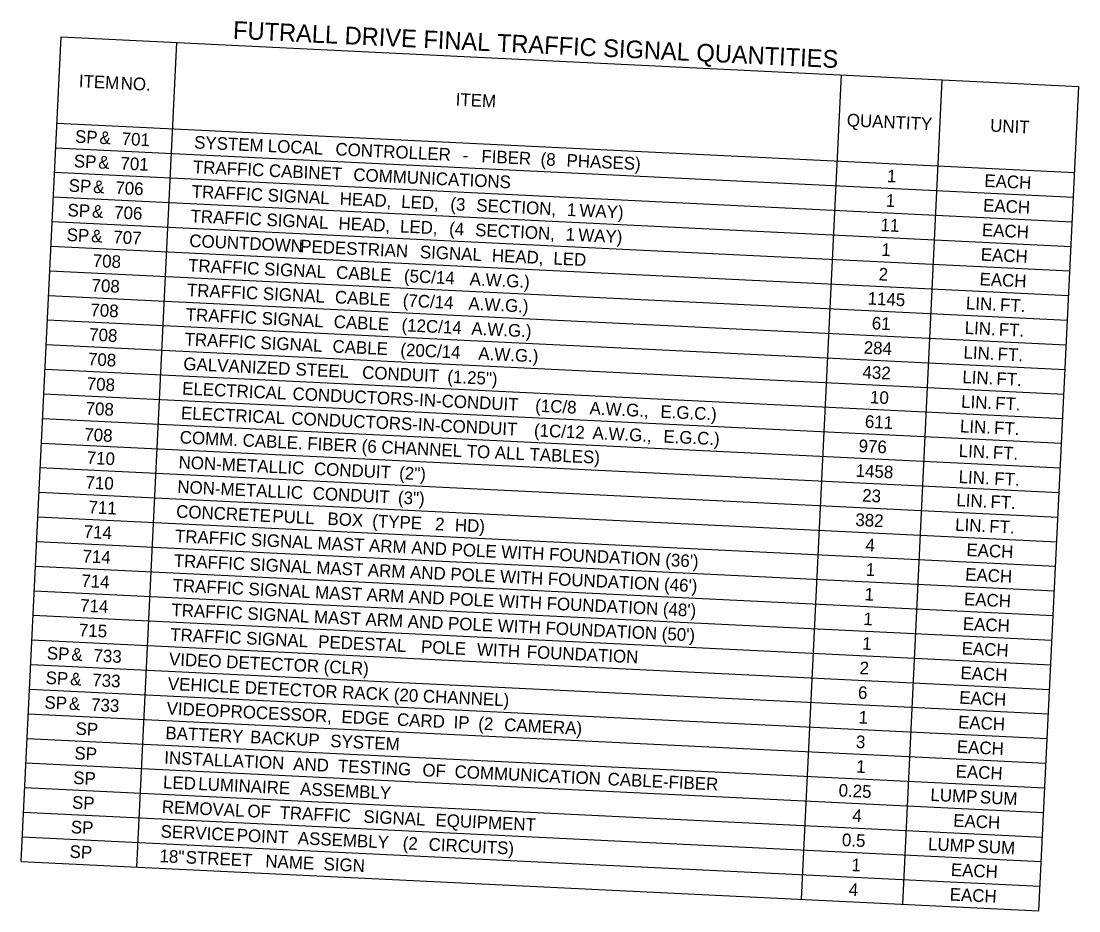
# Model space of a CAD drawing. Extents: x 661018 to 663325, y 642537 to 643074.
# Drawn here: x 661027.9 to 661230.7, y 642822.1 to 642992.7 of the extents above; entities that cross this region are included whole.
import ezdxf

# ---------------------------------------------------------------- set-up
doc = ezdxf.new("R2010")
doc.units = 0
doc.layers.add('R_Border Notes', color=7, linetype='Continuous')

msp = doc.modelspace()

# ---------------------------------------------------------------- linework, layer by layer
at = {"layer": 'R_Border Notes'}
for p, q in [((661027.92, 642831.61), (661035.6, 642989.63)), ((661035.6, 642989.63), (661230.69, 642980.15)), ((661050.12, 642830.53), (661057.77, 642988.55)), ((661177.55, 642824.34), (661185.17, 642982.36)), ((661196.93, 642823.4), (661204.51, 642981.42)), ((661223.01, 642822.13), (661230.69, 642980.15)), ((661034.8, 642973.12), (661229.89, 642963.64)), ((661034.57, 642968.4), (661229.66, 642958.93)), ((661034.34, 642963.68), (661229.43, 642954.21)), ((661034.11, 642958.96), (661229.2, 642949.49)), ((661033.88, 642954.25), (661228.97, 642944.77)), ((661033.65, 642949.53), (661228.74, 642940.06)), ((661033.42, 642944.81), (661228.51, 642935.34)), ((661033.19, 642940.1), (661228.28, 642930.62)), ((661032.96, 642935.38), (661228.05, 642925.91)), ((661032.73, 642930.66), (661227.82, 642921.19)), ((661032.51, 642925.95), (661227.6, 642916.47)), ((661032.51, 642925.95), (661227.6, 642916.47)), ((661032.28, 642921.23), (661227.37, 642911.75)), ((661032.05, 642916.51), (661227.14, 642907.04)), ((661031.82, 642911.79), (661226.91, 642902.32)), ((661031.59, 642907.08), (661226.68, 642897.6)), ((661031.36, 642902.36), (661226.45, 642892.89)), ((661031.13, 642897.64), (661226.22, 642888.17)), ((661030.9, 642892.93), (661225.99, 642883.45)), ((661030.67, 642888.21), (661225.76, 642878.74)), ((661030.44, 642883.49), (661225.53, 642874.02)), ((661030.21, 642878.78), (661225.31, 642869.3)), ((661029.99, 642874.06), (661225.08, 642864.58)), ((661029.76, 642869.34), (661224.85, 642859.87)), ((661029.53, 642864.62), (661224.62, 642855.15)), ((661029.3, 642859.91), (661224.39, 642850.43)), ((661029.07, 642855.19), (661224.16, 642845.72)), ((661029.07, 642855.19), (661224.16, 642845.72)), ((661028.84, 642850.47), (661223.93, 642841)), ((661028.61, 642845.76), (661223.7, 642836.28)), ((661028.38, 642841.04), (661223.47, 642831.57)), ((661028.15, 642836.32), (661223.24, 642826.85)), ((661027.92, 642831.61), (661223.01, 642822.13)), ((661027.92, 642831.61), (661223.01, 642822.13))]:
    msp.add_line(p, q, dxfattribs=at)

# ---------------------------------------------------------------- texts
for s, height, p in [('FUTRALL DRIVE FINAL TRAFFIC SIGNAL QUANTITIES', 3.3906, (661068.48, 642989.29)), ('ITEM', 2.422, (661038.94, 642979.98)), (' NO.', 2.422, (661046.06, 642979.63)), ('ITEM', 2.422, (661111.18, 642976.47)), ('QUANTITY', 2.422, (661186.16, 642972.52)), ('UNIT', 2.422, (661213.64, 642971.49)), ('SP', 2.422, (661038.21, 642969.37)), (' &', 2.422, (661042, 642969.19)), (' 701', 2.422, (661046.25, 642968.98)), ('SYSTEM', 2.422, (661061.04, 642968.26)), (' LOCAL', 2.422, (661074.26, 642967.62)), (' CONTROLLER', 2.4218, (661087.23, 642966.99)), ('SP', 2.422, (661037.98, 642964.66)), (' FIBER', 2.422, (661115.21, 642965.63)), (' (8', 2.422, (661126.56, 642965.08)), (' PHASES)', 2.422, (661131.53, 642964.84)), (' &', 2.422, (661041.77, 642964.47)), (' 701', 2.422, (661046.02, 642964.27)), ('TRAFFIC', 2.422, (661060.81, 642963.55)), (' CABINET', 2.422, (661074.47, 642962.88)), (' -', 2.422, (661111.61, 642965.81)), (' COMMUNICATIONS', 2.4218, (661090.66, 642962.1)), ('1', 2.42, (661193.86, 642961.81)), ('EACH', 2.422, (661212.53, 642960.91)), ('SP', 2.422, (661037, 642959.98)), (' &', 2.422, (661040.79, 642959.79)), (' 706', 2.422, (661045.04, 642959.59)), ('TRAFFIC', 2.422, (661060.58, 642958.83)), (' SIGNAL', 2.422, (661074.24, 642958.17)), (' HEAD,', 2.422, (661088.05, 642957.5)), (' LED,', 2.422, (661099.84, 642956.92)), (' (3', 2.422, (661109.26, 642956.47)), ('1', 2.42, (661193.63, 642957.1)), ('SP', 2.422, (661036.77, 642955.26)), (' &', 2.422, (661040.56, 642955.07)), (' 706', 2.422, (661044.81, 642954.87)), (' SECTION,', 2.422, (661114.24, 642956.23)), (' 1', 2.422, (661131.59, 642955.38)), (' WAY)', 2.422, (661134.01, 642955.27)), ('EACH', 2.422, (661212.3, 642956.19)), ('TRAFFIC', 2.422, (661060.35, 642954.11)), (' SIGNAL', 2.422, (661074.01, 642953.45)), (' HEAD,', 2.422, (661087.82, 642952.78)), ('11', 2.422, (661192.61, 642952.42)), ('SP', 2.422, (661036.61, 642950.54)), (' LED,', 2.422, (661099.61, 642952.21)), (' (4', 2.422, (661109.03, 642951.75)), (' SECTION,', 2.422, (661114.01, 642951.51)), (' 1', 2.422, (661131.36, 642950.67)), (' WAY)', 2.422, (661133.78, 642950.55)), ('EACH', 2.422, (661212.07, 642951.47)), (' &', 2.422, (661040.4, 642950.35)), (' 707', 2.422, (661044.65, 642950.15)), ('COUNTDOWN', 2.422, (661060.12, 642949.4)), (' PEDESTRIAN', 2.4218, (661080.48, 642948.41)), (' SIGNAL', 2.422, (661103.42, 642947.29)), (' HEAD,', 2.422, (661117.22, 642946.62)), ('1', 2.42, (661192.78, 642947.68)), ('EACH', 2.422, (661211.84, 642946.76)), ('708', 2.422, (661041.61, 642945.57)), ('TRAFFIC', 2.422, (661059.89, 642944.68)), (' LED', 2.422, (661129.01, 642946.05)), (' SIGNAL', 2.422, (661073.55, 642944.02)), (' CABLE', 2.422, (661087.36, 642943.35)), (' (5C/14', 2.422, (661100.37, 642942.71)), ('2', 2.42, (661192.26, 642942.98)), ('708', 2.422, (661041.38, 642940.85)), (' A.W.G.)', 2.422, (661112.96, 642942.1)), ('EACH', 2.422, (661211.61, 642942.04)), ('TRAFFIC', 2.422, (661059.66, 642939.96)), (' SIGNAL', 2.422, (661073.32, 642939.3)), (' CABLE', 2.422, (661087.13, 642938.63)), ('1145', 2.422, (661190.15, 642938.35)), (' (7C/14', 2.422, (661100.14, 642938)), (' A.W.G.)', 2.422, (661112.73, 642937.39)), ('LIN.', 2.422, (661208.99, 642937.44)), (' FT.', 2.422, (661214.63, 642937.17)), ('708', 2.422, (661041.15, 642936.13)), ('TRAFFIC', 2.422, (661059.43, 642935.25)), (' SIGNAL', 2.422, (661073.09, 642934.58)), (' CABLE', 2.422, (661086.9, 642933.91)), (' (12C/14', 2.422, (661099.91, 642933.28)), (' A.W.G.)', 2.422, (661113.3, 642932.63)), ('61', 2.422, (661190.95, 642933.59)), ('LIN.', 2.422, (661208.76, 642932.72)), (' FT.', 2.422, (661214.4, 642932.45)), ('708', 2.422, (661040.92, 642931.42)), ('TRAFFIC', 2.422, (661059.21, 642930.53)), (' SIGNAL', 2.422, (661072.86, 642929.87)), (' CABLE', 2.422, (661086.67, 642929.2)), (' (20C/14', 2.422, (661099.68, 642928.56)), ('284', 2.422, (661189.4, 642928.93)), ('708', 2.422, (661040.69, 642926.7)), (' A.W.G.)', 2.422, (661114.63, 642927.84)), ('LIN.', 2.422, (661208.53, 642928.01)), (' FT.', 2.422, (661214.17, 642927.73)), ('GALVANIZED', 2.422, (661058.98, 642925.81)), (' STEEL', 2.422, (661079.57, 642924.81)), (' CONDUIT', 2.422, (661092.35, 642924.19)), ('432', 2.422, (661189.17, 642924.22)), ('708', 2.422, (661040.46, 642921.98)), (' (1.25")', 2.422, (661108.69, 642923.4)), ('LIN.', 2.422, (661208.31, 642923.29)), (' FT.', 2.422, (661213.94, 642923.01)), ('ELECTRICAL', 2.422, (661058.75, 642921.09)), (' CONDUCTORS-IN-CONDUIT', 2.4218, (661079.01, 642920.11)), (' (1C/8', 2.422, (661125.53, 642917.85)), ('10', 2.422, (661190.61, 642919.42)), ('LIN.', 2.422, (661208.08, 642918.57)), (' FT.', 2.422, (661213.71, 642918.3)), ('708', 2.422, (661040.24, 642917.27)), ('ELECTRICAL', 2.422, (661058.52, 642916.38)), (' A.W.G.,', 2.422, (661135.95, 642917.35)), (' E.G.C.)', 2.422, (661149.53, 642916.69)), (' CONDUCTORS-IN-CONDUIT', 2.4218, (661078.78, 642915.39)), ('611', 2.422, (661189.63, 642914.74)), ('LIN.', 2.422, (661207.85, 642913.85)), ('708', 2.422, (661039.99, 642912.26)), (' (1C/12', 2.422, (661125.3, 642913.13)), (' A.W.G.,', 2.422, (661136.52, 642912.59)), (' E.G.C.)', 2.422, (661150.1, 642911.93)), (' FT.', 2.422, (661213.49, 642913.58)), ('COMM. CABLE. FIBER (6 CHANNEL TO ALL TABLES)', 2.4218, (661058.29, 642911.73)), ('976', 2.422, (661188.42, 642910.07)), ('710', 2.422, (661040.45, 642907.8)), ('LIN.', 2.422, (661207.62, 642909.14)), (' FT.', 2.422, (661213.26, 642908.86)), ('NON-METALLIC', 2.4218, (661058.06, 642906.94)), (' CONDUIT', 2.422, (661083.11, 642905.73)), (' (2")', 2.422, (661099.45, 642904.93)), ('1458', 2.422, (661187.86, 642905.34)), ('LIN. FT.', 2.422, (661207.6, 642904.14)), ('710', 2.422, (661040.22, 642903.08)), ('NON-METALLIC', 2.4218, (661057.83, 642902.23)), (' CONDUIT', 2.422, (661082.88, 642901.01)), (' (3")', 2.422, (661099.22, 642900.22)), ('23', 2.422, (661189.11, 642900.58)), ('LIN.', 2.422, (661207.16, 642899.7)), ('711', 2.422, (661040.79, 642898.33)), (' FT.', 2.422, (661212.8, 642899.43)), ('CONCRETE', 2.422, (661057.6, 642897.51)), (' PULL', 2.422, (661075.13, 642896.66)), (' BOX', 2.422, (661085.7, 642896.15)), (' (TYPE', 2.422, (661094.29, 642895.73)), ('382', 2.422, (661187.8, 642895.92)), ('714', 2.422, (661039.87, 642893.64)), (' 2', 2.422, (661106.34, 642895.14)), (' HD)', 2.422, (661110.13, 642894.96)), ('LIN.', 2.422, (661206.93, 642894.99)), (' FT.', 2.422, (661212.57, 642894.71)), ("TRAFFIC SIGNAL MAST ARM AND POLE WITH FOUNDATION (36')", 2.4218, (661057.37, 642892.79)), ('4', 2.42, (661189.74, 642891.09)), ('EACH', 2.422, (661209.09, 642890.15)), ('714', 2.422, (661039.64, 642888.93)), ("TRAFFIC SIGNAL MAST ARM AND POLE WITH FOUNDATION (46')", 2.4218, (661057.14, 642888.08)), ('1', 2.42, (661189.8, 642886.36)), ('714', 2.422, (661039.41, 642884.21)), ('EACH', 2.422, (661208.86, 642885.44)), ("TRAFFIC SIGNAL MAST ARM AND POLE WITH FOUNDATION (48')", 2.4218, (661056.91, 642883.36)), ('1', 2.42, (661189.57, 642881.65)), ('714', 2.422, (661039.18, 642879.49)), ('EACH', 2.422, (661208.63, 642880.72)), ("TRAFFIC SIGNAL MAST ARM AND POLE WITH FOUNDATION (50')", 2.4218, (661056.69, 642878.64)), ('1', 2.42, (661189.34, 642876.93)), ('EACH', 2.422, (661208.41, 642876)), ('715', 2.422, (661038.95, 642874.77)), ('TRAFFIC', 2.422, (661056.46, 642873.92)), (' SIGNAL', 2.422, (661070.11, 642873.26)), (' PEDESTAL', 2.422, (661083.92, 642872.59)), (' POLE', 2.422, (661103.64, 642871.63)), ('1', 2.42, (661189.11, 642872.21)), ('EACH', 2.422, (661208.18, 642871.29)), ('SP', 2.422, (661032.81, 642870.34)), (' &', 2.422, (661036.6, 642870.16)), (' 733', 2.422, (661040.85, 642869.95)), (' WITH', 2.422, (661114.36, 642871.11)), (' FOUNDATION', 2.4218, (661123.9, 642870.65)), ('VIDEO DETECTOR (CLR)', 2.4218, (661056.23, 642869.21)), ('2', 2.42, (661188.6, 642867.51)), ('SP', 2.422, (661032.58, 642865.63)), (' &', 2.422, (661036.37, 642865.44)), (' 733', 2.422, (661040.62, 642865.24)), ('EACH', 2.422, (661207.95, 642866.57)), ('VEHICLE DETECTOR RACK (20 CHANNEL)', 2.4218, (661056, 642864.49)), ('6', 2.42, (661188.3, 642862.79)), ('EACH', 2.422, (661207.72, 642861.85)), ('SP', 2.422, (661032.35, 642860.91)), (' &', 2.422, (661036.14, 642860.73)), (' 733', 2.422, (661040.39, 642860.52)), ('VIDEO', 2.422, (661055.77, 642859.77)), (' PROCESSOR,', 2.4218, (661064.97, 642859.33)), (' EDGE', 2.422, (661088.38, 642858.19)), (' CARD', 2.422, (661099.03, 642857.67)), (' IP', 2.422, (661109.88, 642857.15)), ('1', 2.42, (661188.42, 642858.06)), ('EACH', 2.422, (661207.49, 642857.13)), ('SP', 2.422, (661038.31, 642855.89)), ('BATTERY', 2.422, (661055.54, 642855.06)), (' (2', 2.422, (661114.61, 642856.92)), (' CAMERA)', 2.422, (661119.58, 642856.67)), (' BACKUP', 2.422, (661070.89, 642854.31)), (' SYSTEM', 2.422, (661086.24, 642853.57)), ('3', 2.42, (661187.91, 642853.36)), ('SP', 2.422, (661038.09, 642851.18)), ('EACH', 2.422, (661207.26, 642852.42)), ('INSTALLATION', 2.4218, (661055.31, 642850.34)), (' AND', 2.422, (661079.14, 642849.18)), (' TESTING', 2.422, (661087.71, 642848.77)), (' OF', 2.422, (661103.9, 642847.98)), (' COMMUNICATION', 2.4218, (661110.07, 642847.68)), ('1', 2.42, (661187.97, 642848.63)), ('EACH', 2.422, (661207.03, 642847.7)), ('SP', 2.422, (661037.86, 642846.46)), ('LED', 2.422, (661055.08, 642845.62)), (' LUMINAIRE', 2.422, (661060.93, 642845.34)), (' CABLE-FIBER', 2.4218, (661139.4, 642846.26)), (' ASSEMBLY', 2.422, (661080.45, 642844.39)), ('0.25', 2.422, (661184.59, 642844.06)), ('LUMP', 2.422, (661202.19, 642843.21)), ('SP', 2.422, (661037.63, 642841.74)), ('REMOVAL', 2.422, (661054.85, 642840.91)), (' SUM', 2.422, (661210.78, 642842.79)), (' OF', 2.422, (661070.36, 642840.15)), (' TRAFFIC', 2.422, (661076.53, 642839.85)), (' SIGNAL', 2.422, (661092.6, 642839.07)), ('4', 2.42, (661187.22, 642839.21)), ('SP', 2.422, (661037.4, 642837.02)), (' EQUIPMENT', 2.422, (661106.41, 642838.4)), ('EACH', 2.422, (661206.57, 642838.27)), ('SERVICE', 2.422, (661054.62, 642836.19)), (' POINT', 2.422, (661068.3, 642835.52)), (' ASSEMBLY', 2.422, (661080.03, 642834.95)), (' (2', 2.422, (661100.13, 642833.98)), (' CIRCUITS)', 2.422, (661105.1, 642833.74)), ('0.5', 2.422, (661185.22, 642834.57)), ('LUMP', 2.422, (661201.73, 642833.77)), (' SUM', 2.422, (661210.32, 642833.36)), ('SP', 2.422, (661037.17, 642832.31)), ('18"', 2.422, (661054.4, 642831.47)), (' STREET', 2.422, (661058.53, 642831.27)), (' NAME', 2.422, (661073.8, 642830.53)), (' SIGN', 2.422, (661084.95, 642829.99)), ('1', 2.42, (661187.05, 642829.76)), ('EACH', 2.422, (661206.11, 642828.83)), ('4', 2.42, (661186.54, 642825.05)), ('EACH', 2.422, (661205.89, 642824.12))]:
    msp.add_text(s, height=height, rotation=357.2199, dxfattribs=at).set_placement(p)

doc.saveas('drawing.dxf')
